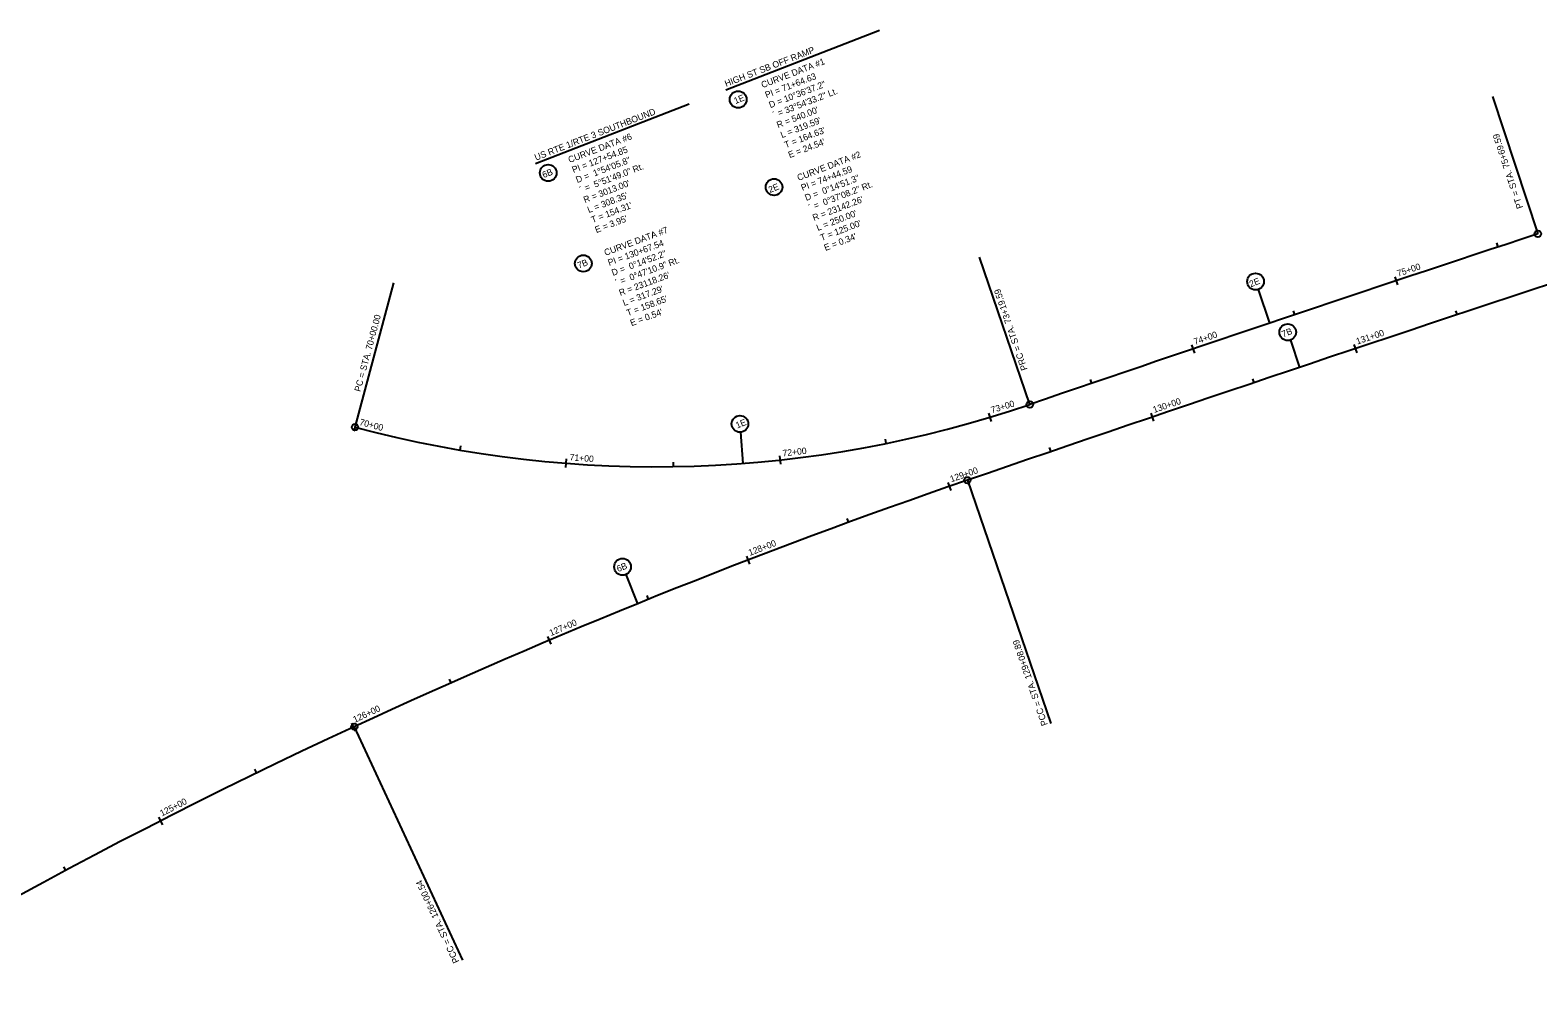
# Model space of a CAD drawing. Extents: x 1667099 to 1669772, y 337408 to 340124.
# Drawn here: x 1668571 to 1669274, y 339527 to 339970 of the extents above; entities that cross this region are included whole.
import ezdxf

# ---------------------------------------------------------------- set-up
doc = ezdxf.new("R2010")
doc.units = 0
for name, color, linetype in [('Alignment', 7, 'Continuous'), ('ANNOTATION', 7, 'Continuous'), ('D_Roadway_Centerline', 7, 'Continuous'), ('D_Roadway_Centerline_CurveData', 7, 'Continuous'), ('D_Roadway_Centerline_Flags', 7, 'Continuous'), ('D_Roadway_Centerline_Text', 7, 'Continuous'), ('S_Roadway_Edge_Pavement', 7, 'Continuous')]:
    doc.layers.add(name, color=color, linetype=linetype)

msp = doc.modelspace()

# ---------------------------------------------------------------- linework, layer by layer
at = {"layer": 'Alignment'}
for centre, radius, start, end in [((1676524.41, 317897.9), 23142.26, 108.258083, 108.877034), ((1668862.29, 340306.42), 540, 254.96782, 288.87703)]:
    msp.add_arc(centre, radius, start, end, dxfattribs=at)
at = {"layer": 'ANNOTATION'}
for p, q in [((1668895.17, 339942.29), (1668966.89, 339970.11)), ((1668806.47, 339907.88), (1668878.18, 339935.7)), ((1669143.56, 339849.1), (1669148.84, 339833.38)), ((1669158.55, 339825.47), (1669162.82, 339812.76)), ((1668902.11, 339782.48), (1668903.21, 339767.97)), ((1668848.52, 339716.08), (1668854.04, 339702.48))]:
    msp.add_line(p, q, dxfattribs=at)
for centre in [(1668900.97, 339937.75), (1668812.36, 339903.49), (1668917.71, 339896.89), (1668828.74, 339861.25), (1669142.31, 339852.8), (1669157.31, 339829.17), (1668901.81, 339786.37), (1668847.05, 339719.7)]:
    msp.add_circle(centre, 3.9, dxfattribs=at)
at = {"layer": 'D_Roadway_Centerline'}
for centre, radius, start, end in [((1676524.41, 317897.9), 23142.26, 108.258083, 108.877034), ((1676524.41, 317897.9), 23118.26, 108.187357, 108.973714), ((1668862.29, 340306.42), 540, 254.96782, 288.87703), ((1669987.5, 336910.8), 3013, 108.97371, 114.83733), ((1669819.48, 337273.8), 2613, 114.83733, 133.776)]:
    msp.add_arc(centre, radius, start, end, dxfattribs=at)
at = {"layer": 'D_Roadway_Centerline_Flags'}
for points in [[(1669252.85, 339939.13), (1669273.99, 339875.07)], [(1669037, 339795.46), (1669013.49, 339864.24)], [(1668722.24, 339784.89), (1668740.33, 339852.27)], [(1669007.87, 339760.1), (1669046.88, 339646.62)], [(1668721.91, 339645.11), (1668772.31, 339536.21)]]:
    msp.add_lwpolyline(points, dxfattribs=at)
for centre in [(1669273.99, 339875.07), (1669037, 339795.46), (1668722.24, 339784.89), (1669007.87, 339760.1), (1668721.91, 339645.11)]:
    msp.add_circle(centre, 1.5, dxfattribs=at)
at = {"layer": 'D_Roadway_Centerline_Text'}
for points in [[(1669254.76, 339870.82), (1669255.39, 339868.92)], [(1669207.3, 339855.06), (1669208.57, 339851.27)], [(1669159.88, 339839.2), (1669160.52, 339837.31)], [(1669235.65, 339839.2), (1669236.28, 339837.3)], [(1669112.49, 339823.24), (1669113.78, 339819.45)], [(1669188.21, 339823.38), (1669189.48, 339819.59)], [(1669065.14, 339807.17), (1669065.79, 339805.28)], [(1669140.81, 339807.47), (1669141.45, 339805.57)], [(1669017.78, 339791.38), (1669018.94, 339787.55)], [(1669093.44, 339791.45), (1669094.73, 339787.66)], [(1668722.75, 339786.83), (1668721.72, 339782.96)], [(1668771.39, 339776.15), (1668771.06, 339774.18)], [(1668969.49, 339779.2), (1668969.89, 339777.24)], [(1669046.11, 339775.32), (1669046.75, 339773.43)], [(1668820.81, 339770.02), (1668820.5, 339766.03)], [(1668870.59, 339768.48), (1668870.62, 339766.48)], [(1668920.29, 339771.55), (1668920.72, 339767.57)], [(1668998.81, 339759.09), (1669000.12, 339755.31)], [(1668951.68, 339742.29), (1668952.37, 339740.41)], [(1668904.84, 339724.71), (1668906.27, 339720.98)], [(1668858.29, 339706.36), (1668859.04, 339704.5)], [(1668812.06, 339687.23), (1668813.62, 339683.55)], [(1668766.15, 339667.35), (1668766.96, 339665.52)], [(1668720.57, 339646.7), (1668722.25, 339643.07)], [(1668675.37, 339625.24), (1668676.25, 339623.44)], [(1668630.59, 339602.92), (1668632.41, 339599.35)], [(1668586.24, 339579.74), (1668587.19, 339577.98)]]:
    msp.add_lwpolyline(points, dxfattribs=at)
at = {"layer": 'S_Roadway_Edge_Pavement'}
for centre, radius, start, end in [((1676524.41, 317897.9), 23118.26, 108.187357, 108.973714), ((1669987.5, 336910.8), 3013, 108.97371, 114.83733), ((1669819.48, 337273.8), 2613, 114.83733, 133.776)]:
    msp.add_arc(centre, radius, start, end, dxfattribs=at)

# ---------------------------------------------------------------- texts
at = {"layer": 'ANNOTATION'}
for s, rotation, p in [('HIGH ST SB OFF RAMP', 21.20129, (1668895.36, 339943.59)), ('1E', 21.90532, (1668899.7, 339935.59)), ('US RTE 1/RTE 3 SOUTHBOUND', 21.20129, (1668806.65, 339909.18)), ('6B', 21.90532, (1668810.29, 339901.02)), ('2E', 21.90532, (1668915.79, 339894.11)), ('7B', 21.90532, (1668826.67, 339858.78)), ('2E', 21.90532, (1669140.11, 339850.09)), ('7B', 21.90532, (1669155.24, 339826.7)), ('1E', 21.90532, (1668900.54, 339784.21)), ('6B', 21.90532, (1668844.98, 339717.22))]:
    msp.add_text(s, height=3, rotation=rotation, dxfattribs=at).set_placement(p)
at = {"layer": 'D_Roadway_Centerline_CurveData'}
for s, rotation, p in [('CURVE DATA #1', 21.12983, (1668912.39, 339943.02)), ('PI = 71+64.63', 21.12983, (1668914.19, 339938.36)), ('D = 10%%d36\'37.2"', 21.12983, (1668915.99, 339933.69)), ('´ = 33%%d54\'33.2" Lt.', 21.12983, (1668917.8, 339929.03)), ("R = 540.00'", 21.12983, (1668919.6, 339924.37)), ("L = 319.59'", 21.12983, (1668921.4, 339919.7)), ("T = 164.63'", 21.12983, (1668923.2, 339915.04)), ('CURVE DATA #6', 20.9247, (1668822.35, 339908.09)), ('PI = 127+54.85', 20.9247, (1668824.14, 339903.42)), ("E = 24.54'", 21.12983, (1668925.01, 339910.37)), ('D =  1%%d54\'05.8"', 20.9247, (1668825.92, 339898.75)), ('CURVE DATA #2', 20.98014, (1668929.17, 339899.73)), ('´ =  5%%d51\'49.0" Rt.', 20.9247, (1668827.71, 339894.08)), ('PI = 74+44.59', 20.98014, (1668930.96, 339895.06)), ('D =  0%%d14\'51.3"', 20.98014, (1668932.75, 339890.39)), ("R = 3013.00'", 20.9247, (1668829.49, 339889.41)), ('´ =  0%%d37\'08.2" Rt.', 20.98014, (1668934.54, 339885.72)), ("L = 308.35'", 20.9247, (1668831.28, 339884.74)), ("T = 154.31'", 20.9247, (1668833.06, 339880.07)), ("R = 23142.26'", 20.98014, (1668936.34, 339881.05)), ("E = 3.95'", 20.9247, (1668834.85, 339875.4)), ("L = 250.00'", 20.98014, (1668938.13, 339876.38)), ("T = 125.00'", 20.98014, (1668939.92, 339871.71)), ('CURVE DATA #7', 20.3319, (1668839.09, 339864.78)), ("E = 0.34'", 20.98014, (1668941.71, 339867.05)), ('PI = 130+67.54', 20.3319, (1668840.83, 339860.09)), ('D =  0%%d14\'52.2"', 20.3319, (1668842.57, 339855.41)), ('´ =  0%%d47\'10.9" Rt.', 20.3319, (1668844.3, 339850.72)), ("R = 23118.26'", 20.3319, (1668846.04, 339846.03)), ("L = 317.29'", 20.3319, (1668847.78, 339841.34)), ("T = 158.65'", 20.3319, (1668849.52, 339836.65)), ("E = 0.54'", 20.3319, (1668851.25, 339831.96))]:
    msp.add_text(s, height=3, rotation=rotation, dxfattribs=at).set_placement(p)
at = {"layer": 'D_Roadway_Centerline_Flags'}
for s, rotation, p in [('PT = STA. 75+69.59', 108.25808, (1669267.17, 339887.36)), ('PRC = STA. 73+19.59', 108.87703, (1669035.98, 339811.9)), ('PC = STA. 70+00.00', 74.96782, (1668724.77, 339801.18)), ('PCC = STA. 129+08.89', 108.97371, (1669045.46, 339646.13)), ('PCC = STA. 126+00.54', 114.83733, (1668770.95, 339535.58))]:
    msp.add_text(s, height=3, rotation=rotation, dxfattribs=at).set_placement(p)
at = {"layer": 'D_Roadway_Centerline_Text'}
for s, rotation, p in [('75+00', 18.43037, (1669208.89, 339855.06)), ('74+00', 18.67795, (1669114.08, 339823.25)), ('131+00', 18.50007, (1669189.79, 339823.39)), ('73+00', 16.79881, (1669019.36, 339791.33)), ('130+00', 18.74791, (1669095.02, 339791.45)), ('70+00', 344.96782, (1668724.07, 339785.95)), ('72+00', 6.18848, (1668921.83, 339771.22)), ('71+00', 355.57815, (1668822.27, 339769.4)), ('129+00', 19.14276, (1669000.39, 339759.11)), ('128+00', 21.04438, (1668906.42, 339724.78)), ('127+00', 22.946, (1668813.63, 339687.36)), ('126+00', 24.84919, (1668722.15, 339646.88)), ('125+00', 27.04191, (1668632.15, 339603.15))]:
    msp.add_text(s, height=3, rotation=rotation, dxfattribs=at).set_placement(p)

doc.saveas('drawing.dxf')
